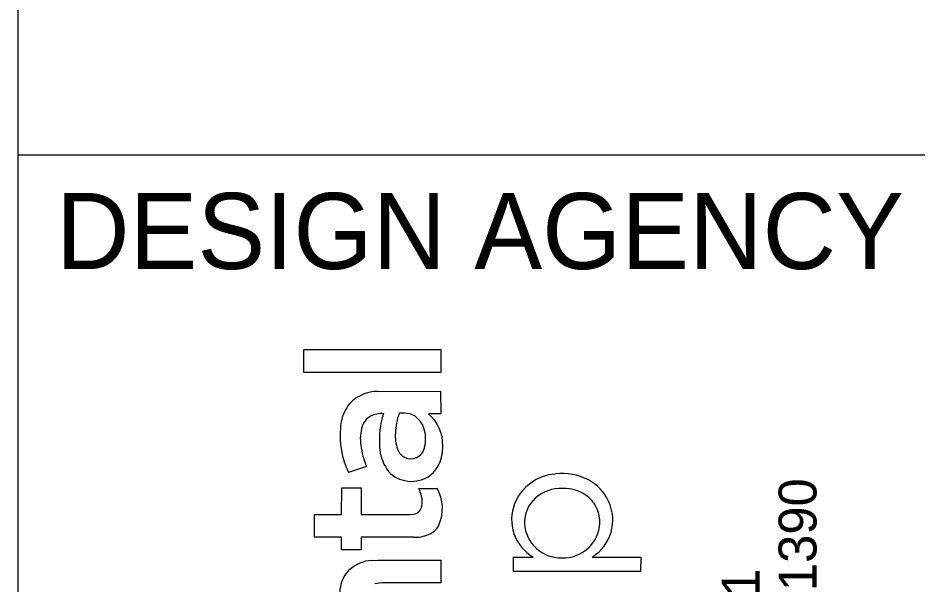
# Model space of a CAD drawing. Extents: x -0.4 to 34, y 0 to 22.
# Drawn here: x 32 to 33.183, y 4.436 to 5.18 of the extents above; entities that cross this region are included whole.
import ezdxf

# ---------------------------------------------------------------- set-up
doc = ezdxf.new("R2010")
doc.units = 0
doc.layers.add('SH_Border', color=7, linetype='Continuous')
doc.layers.add('SH_Data', color=7, linetype='Continuous')

msp = doc.modelspace()

# ---------------------------------------------------------------- linework, layer by layer
at = {"layer": 'SH_Border'}
for p, q in [((32, 0.5), (32, 21.5)), ((32, 5), (33.5, 5))]:
    msp.add_line(p, q, dxfattribs=at)
at = {"layer": 'SH_Data'}
for p, q in [((32.3756, 4.7141), (32.3756, 4.744)), ((32.3756, 4.744), (32.5557, 4.744)), ((32.5557, 4.744), (32.5557, 4.7141)), ((32.5557, 4.7141), (32.3756, 4.7141)), ((32.4727, 4.689), (32.5555, 4.6892)), ((32.5555, 4.6892), (32.5557, 4.6596)), ((32.5557, 4.6596), (32.5397, 4.6596)), ((32.4582, 4.5904), (32.4343, 4.5823)), ((32.4254, 4.527), (32.4255, 4.5621)), ((32.4255, 4.5621), (32.4511, 4.5621)), ((32.4511, 4.5621), (32.4512, 4.527)), ((32.527, 4.5616), (32.5511, 4.5616)), ((32.3896, 4.4972), (32.3896, 4.527)), ((32.3896, 4.527), (32.4254, 4.527)), ((32.4512, 4.527), (32.515, 4.527)), ((32.515, 4.527), (32.52, 4.5275)), ((32.4254, 4.4972), (32.3896, 4.4972)), ((32.4254, 4.4807), (32.4254, 4.4972)), ((32.5197, 4.4972), (32.4511, 4.4972)), ((32.4511, 4.4972), (32.4511, 4.4807)), ((32.4511, 4.4807), (32.4254, 4.4807)), ((32.4644, 4.4669), (32.4729, 4.4673)), ((32.4729, 4.4673), (32.5557, 4.4673)), ((32.5557, 4.4673), (32.5557, 4.4375)), ((32.6515, 4.4521), (32.6515, 4.4711)), ((32.6515, 4.4711), (32.6771, 4.4711)), ((32.7549, 4.4713), (32.8186, 4.4711)), ((32.8186, 4.4711), (32.8184, 4.4521)), ((32.8184, 4.4521), (32.6515, 4.4521)), ((32.5557, 4.4375), (32.4814, 4.4375))]:
    msp.add_line(p, q, dxfattribs=at)
msp.add_lwpolyline([(32.3756, 4.7141), (32.3756, 4.744), (32.5557, 4.744), (32.5557, 4.7141)], close=True, dxfattribs=at)
for points in [[(32.4727, 4.689), (32.5555, 4.6892), (32.5557, 4.6596)], [(32.5557, 4.6596), (32.5397, 4.6596)], [(32.4582, 4.5904), (32.4343, 4.5823)], [(32.5197, 4.4972), (32.4511, 4.4972), (32.4511, 4.4807), (32.4254, 4.4807), (32.4254, 4.4972), (32.3896, 4.4972), (32.3896, 4.527), (32.4254, 4.527), (32.4255, 4.5621), (32.4511, 4.5621), (32.4512, 4.527), (32.515, 4.527), (32.52, 4.5275)], [(32.527, 4.5616), (32.5511, 4.5616)], [(32.4644, 4.4669), (32.4729, 4.4673), (32.5557, 4.4673), (32.5557, 4.4375), (32.4814, 4.4375)], [(32.7549, 4.4713), (32.8186, 4.4711), (32.8184, 4.4521), (32.6515, 4.4521)], [(32.6515, 4.4521), (32.6515, 4.4711), (32.6771, 4.4711)]]:
    msp.add_lwpolyline(points, dxfattribs=at)
for centre, radius, start, end in [((32.4745, 4.6326), 0.0565, 91.8942, 122.6317), ((32.4745, 4.6326), 0.0565, 91.8942, 122.6317), ((32.4685, 4.6447), 0.043, 124.537, 155.6594), ((32.4685, 4.6447), 0.043, 124.537, 155.6594), ((32.4882, 4.6361), 0.0646, 155.9764, 175.3149), ((32.4882, 4.6361), 0.0646, 155.9764, 175.3149), ((32.4753, 4.6356), 0.024, 119.4252, 161.6629), ((32.4753, 4.6356), 0.024, 119.4252, 161.6629), ((32.4779, 4.6278), 0.0321, 85.3802, 116.6222), ((32.4779, 4.6278), 0.0321, 85.3802, 116.6222), ((32.5879, 4.6251), 0.1129, 162.0821, 184.5285), ((32.5879, 4.6251), 0.1129, 162.0821, 184.5285), ((32.5801, 4.6313), 0.0841, 159.8366, 178.0362), ((32.5801, 4.6313), 0.0841, 159.8366, 178.0362), ((32.5051, 4.6074), 0.053, 79.6696, 94.2322), ((32.5051, 4.6074), 0.053, 79.6696, 94.2322), ((32.5089, 4.6364), 0.0238, 56.8913, 76.2149), ((32.5089, 4.6364), 0.0238, 56.8913, 76.2149), ((32.5052, 4.6318), 0.0297, 17.5984, 55.7282), ((32.5052, 4.6318), 0.0297, 17.5984, 55.7282), ((32.5055, 4.6191), 0.0529, 358.0746, 49.762), ((32.5055, 4.6191), 0.0529, 358.0746, 49.762), ((32.5364, 4.6308), 0.113, 174.6101, 205.3899), ((32.5364, 4.6308), 0.113, 174.6101, 205.3899), ((32.5076, 4.6265), 0.0576, 163.1369, 188.1675), ((32.5076, 4.6265), 0.0576, 163.1369, 188.1675), ((32.4916, 4.6264), 0.0443, 345.9408, 18.9919), ((32.4916, 4.6264), 0.0443, 345.9408, 18.9919), ((32.5466, 4.6303), 0.0506, 175.5903, 199.8857), ((32.5466, 4.6303), 0.0506, 175.5903, 199.8857), ((32.5473, 4.6297), 0.0973, 186.7598, 203.7981), ((32.5473, 4.6297), 0.0973, 186.7598, 203.7981), ((32.5328, 4.6187), 0.0575, 182.5676, 213.7144), ((32.5328, 4.6187), 0.0575, 182.5676, 213.7144), ((32.5152, 4.6199), 0.0199, 295.2883, 347.4639), ((32.5152, 4.6199), 0.0199, 295.2883, 347.4639), ((32.5019, 4.6168), 0.0566, 336.016, 0.5951), ((32.5019, 4.6168), 0.0566, 336.016, 0.5951), ((32.5164, 4.6189), 0.0184, 198.2844, 293.3081), ((32.5164, 4.6189), 0.0184, 198.2844, 293.3081), ((32.5175, 4.6097), 0.0394, 303.4436, 336.18), ((32.5175, 4.6097), 0.0394, 303.4436, 336.18), ((32.5149, 4.6078), 0.0366, 215.0668, 259.8133), ((32.5149, 4.6078), 0.0366, 215.0668, 259.8133), ((32.7108, 4.5182), 0.0624, 93.9866, 158.3119), ((32.7108, 4.5182), 0.0624, 93.9866, 158.3119), ((32.7156, 4.5065), 0.0746, 62.6889, 97.0135), ((32.7156, 4.5065), 0.0746, 62.6889, 97.0135), ((32.5175, 4.6131), 0.0423, 257.5256, 300.882), ((32.5175, 4.6131), 0.0423, 257.5256, 300.882), ((32.7212, 4.5191), 0.0608, 25.0657, 61.9602), ((32.7212, 4.5191), 0.0608, 25.0657, 61.9602), ((32.4863, 4.542), 0.0452, 10.1545, 25.723), ((32.4863, 4.542), 0.0452, 10.1545, 25.723), ((32.503, 4.5351), 0.0549, 336.589, 28.8991), ((32.503, 4.5351), 0.0549, 336.589, 28.8991), ((32.7138, 4.5102), 0.0513, 87.8965, 131.1812), ((32.7138, 4.5102), 0.0513, 87.8965, 131.1812), ((32.7175, 4.5102), 0.0513, 49.9089, 92.0363), ((32.7175, 4.5102), 0.0513, 49.9089, 92.0363), ((32.4957, 4.5436), 0.0356, 351.914, 10.2059), ((32.4957, 4.5436), 0.0356, 351.914, 10.2059), ((32.7092, 4.5167), 0.0434, 132.3289, 182.0949), ((32.7092, 4.5167), 0.0434, 132.3289, 182.0949), ((32.7215, 4.5173), 0.0433, 358.0487, 47.9447), ((32.7215, 4.5173), 0.0433, 358.0487, 47.9447), ((32.7245, 4.52), 0.0574, 301.9776, 25.6418), ((32.7245, 4.52), 0.0574, 301.9776, 25.6418), ((32.5184, 4.54), 0.0126, 277.6142, 353.7918), ((32.5184, 4.54), 0.0126, 277.6142, 353.7918), ((32.707, 4.5202), 0.0581, 158.656, 198.171), ((32.707, 4.5202), 0.0581, 158.656, 198.171), ((32.5291, 4.5261), 0.0275, 292.6889, 332.0598), ((32.5291, 4.5261), 0.0275, 292.6889, 332.0598), ((32.7135, 4.5181), 0.0478, 183.5974, 271.7045), ((32.7135, 4.5181), 0.0478, 183.5974, 271.7045), ((32.7172, 4.518), 0.0477, 267.3149, 357.4019), ((32.7172, 4.518), 0.0477, 267.3149, 357.4019), ((32.5209, 4.5486), 0.0514, 268.6727, 291.5235), ((32.5209, 4.5486), 0.0514, 268.6727, 291.5235), ((32.7103, 4.5243), 0.0627, 200.8399, 238.0162), ((32.7103, 4.5243), 0.0627, 200.8399, 238.0162), ((32.4687, 4.4172), 0.0499, 94.9706, 130.2248), ((32.4687, 4.4172), 0.0499, 94.9706, 130.2248), ((32.4635, 4.4255), 0.0402, 132.2238, 161.6823), ((32.4635, 4.4255), 0.0402, 132.2238, 161.6823), ((32.4787, 4.4211), 0.056, 162.274, 187.7917), ((32.4787, 4.4211), 0.056, 162.274, 187.7917), ((32.4811, 4.3915), 0.046, 89.6051, 105.3303), ((32.4811, 4.3915), 0.046, 89.6051, 105.3303)]:
    msp.add_arc(centre, radius, start, end, dxfattribs=at)

# ---------------------------------------------------------------- texts
msp.add_text('DESIGN AGENCY', height=0.1, dxfattribs=at).set_placement((32.05, 4.85))
for s, p in [('800.835.1390', (33.0497, 4.1671)), ('450 GRANT ST., AKRON, OH  44311', (32.9749, 3.3374))]:
    msp.add_text(s, height=0.049846, rotation=90, dxfattribs=at).set_placement(p)

doc.saveas('drawing.dxf')
